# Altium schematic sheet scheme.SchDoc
size A
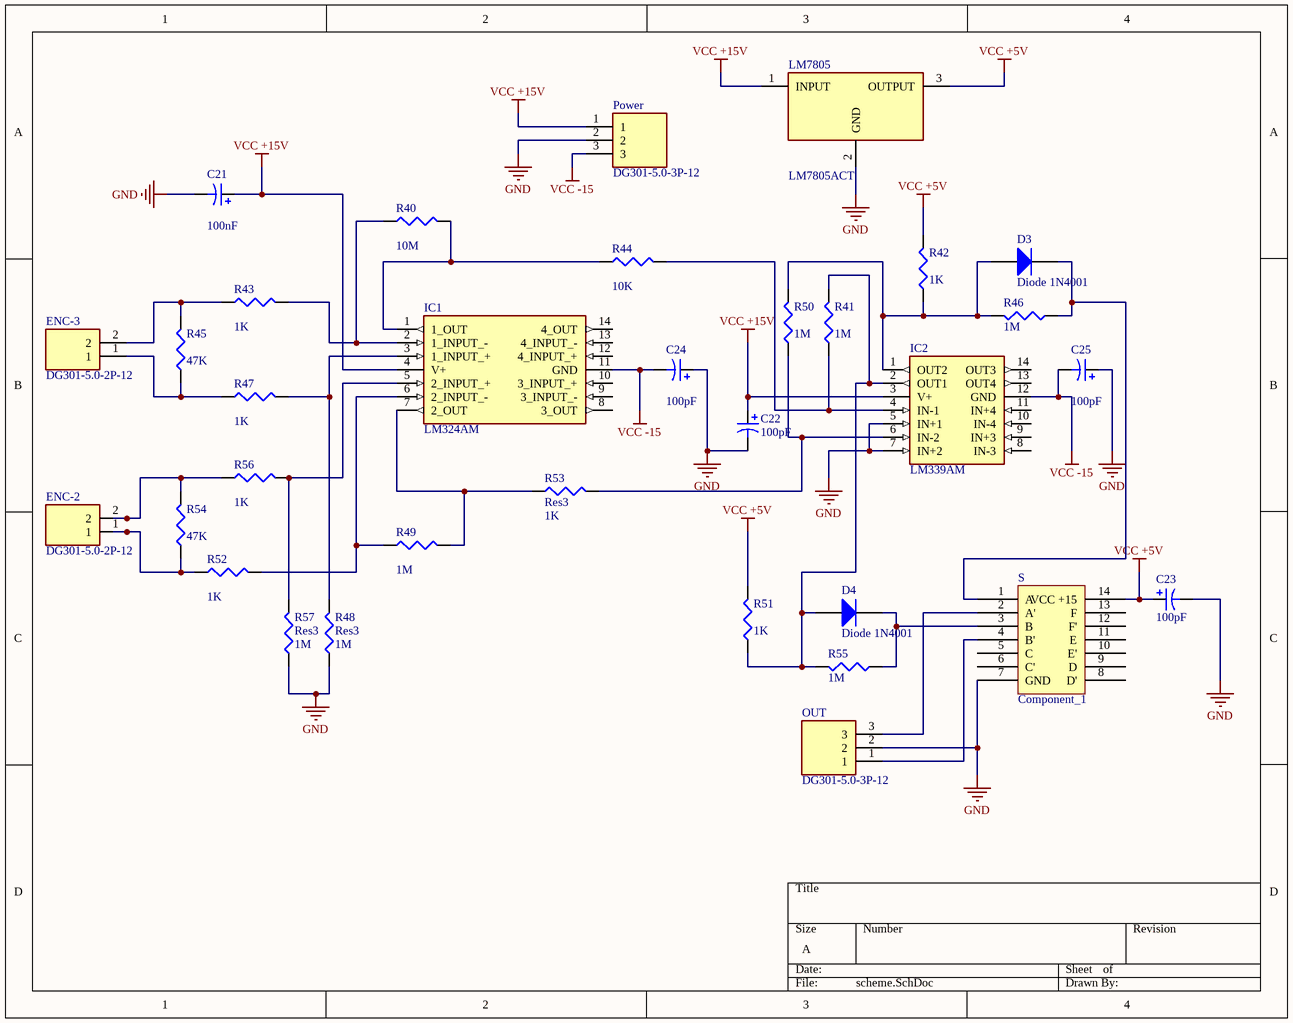
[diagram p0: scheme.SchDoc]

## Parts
C21  value 100nF  [C1206]  (hidden comment: Cap Pol3)
C22  value 100pF  [C1206]  (hidden comment: Cap Pol3)
C23  value 100pF  [C1206]  (hidden comment: Cap Pol3)
C24  value 100pF  [C1206]  (hidden comment: Cap Pol3)
C25  value 100pF  [C1206]  (hidden comment: Cap Pol3)
D3  Diode 1N4001  [SOT23_N]
D4  Diode 1N4001  [SOT23_N]
ENC-2  DG301-5.0-2P-12  [SHDR2W110P0X500_1X2_1000X760X1000P]
ENC-3  DG301-5.0-2P-12  [SHDR2W110P0X500_1X2_1000X760X1000P]
IC1  LM324AM  [SOIC127P600X175-14N]
IC2  LM339AM  [SOIC127P600X175-14N]
LM7805  LM7805ACT  [TO254P470X1016X2019-3P]
OUT  DG301-5.0-3P-12  [SHDR3W110P0X500_1X3_1500X760X1000P]
Power  DG301-5.0-3P-12  [SHDR3W110P0X500_1X3_1500X760X1000P]
R40  value 10M  [C1206]  (hidden comment: Res3)
R41  value 1M  [C1206]  (hidden comment: Res3)
R42  value 1K  [C1206]  (hidden comment: Res3)
R43  value 1K  [C1206]  (hidden comment: Res3)
R44  value 10K  [C1206]  (hidden comment: Res3)
R45  value 47K  [C1206]  (hidden comment: Res3)
R46  value 1M  [C1206]  (hidden comment: Res3)
R47  value 1K  [C1206]  (hidden comment: Res3)
R48  Res3  value 1M  [C1206]
R49  value 1M  [C1206]  (hidden comment: Res3)
R50  value 1M  [C1206]  (hidden comment: Res3)
R51  value 1K  [C1206]  (hidden comment: Res3)
R52  value 1K  [C1206]  (hidden comment: Res3)
R53  Res3  value 1K  [C1206]
R54  value 47K  [C1206]  (hidden comment: Res3)
R55  value 1M  [C1206]  (hidden comment: Res3)
R56  value 1K  [C1206]  (hidden comment: Res3)
R57  Res3  value 1M  [C1206]
S  Component_1  [SOIC127P600X175-14N]

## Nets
GND: C21.2 C22.2 C23.2 C24.1 C25.1 IC2.5(IN+1) IC2.7(IN+2) LM7805.2(GND) OUT.2 Power.2 R48.1 R57.1 S.7(GND)
VCC +5V: C23.1 LM7805.3(OUTPUT) R42.2 R51.2 S.14(VCC_+15)
VCC +15V: C21.1 C22.1 IC1.4(V+) IC2.3(V+) LM7805.1(INPUT) Power.1
VCC -15: C24.2 C25.2 IC1.11(GND) IC2.12(GND) Power.3
NetD3_1: D3.1(A) IC2.1(OUT2) R42.1 R46.2 R50.2
NetD3_2: D3.2(K) R46.1 S.1(A)
NetD4_1: D4.1(A) IC2.2(OUT1) R41.2 R51.1 R55.2
NetD4_2: D4.2(K) R55.1 S.3(B)
NetENC-2_1: ENC-2.1 R52.1 R54.1
NetENC-2_2: ENC-2.2 R54.2 R56.1
NetENC-3_1: ENC-3.1 R45.1 R47.1
NetENC-3_2: ENC-3.2 R43.1 R45.2
NetIC1_1: IC1.1(1_OUT) R40.2 R44.1
NetIC1_2: IC1.2(1_INPUT_-) R40.1 R43.2
NetIC1_3: IC1.3(1_INPUT_+) R47.2 R48.2
NetIC1_5: IC1.5(2_INPUT_+) R56.2 R57.2
NetIC1_6: IC1.6(2_INPUT_-) R49.1 R52.2
NetIC1_7: IC1.7(2_OUT) R49.2 R53.1
NetIC2_4: IC2.4(IN-1) R41.1 R44.2
NetIC2_6: IC2.6(IN-2) R50.1 R53.2
NetOUT_1: OUT.1 S.4(B')
NetOUT_3: OUT.3 S.2(A')

Not connected (* = marked no-connect by the designer): IC1 8(3_OUT) 9(3_INPUT_-) 10(3_INPUT_+) 12(4_INPUT_+) 13(4_INPUT_-) 14(4_OUT); IC2 8(IN-3) 9(IN+3) 10(IN-4) 11(IN+4) 13(OUT4) 14(OUT3); S 5(C) 6(C') 8(D') 9(D) 10(E') 11(E) 12(F') 13(F)

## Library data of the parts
C21-C25 = Cap Pol3: Polarized Capacitor (Surface Mount)
D3 D4 = Diode 1N4001: 1 Amp General Purpose Rectifier
ENC-2 ENC-3 = DG301-5.0-2P-12: Connector; Manufacturer_Name: Degson
IC1 = LM324AM: Integrated Circuit; Manufacturer_Name: Texas Instruments
IC2 = LM339AM: Integrated Circuit; Manufacturer_Name: Texas Instruments
LM7805 = LM7805ACT: Integrated Circuit; Manufacturer_Name: Fairchild Semiconductor
OUT Power = DG301-5.0-3P-12: Connector; Manufacturer_Name: Degson
R40-R57 = Res3: Resistor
